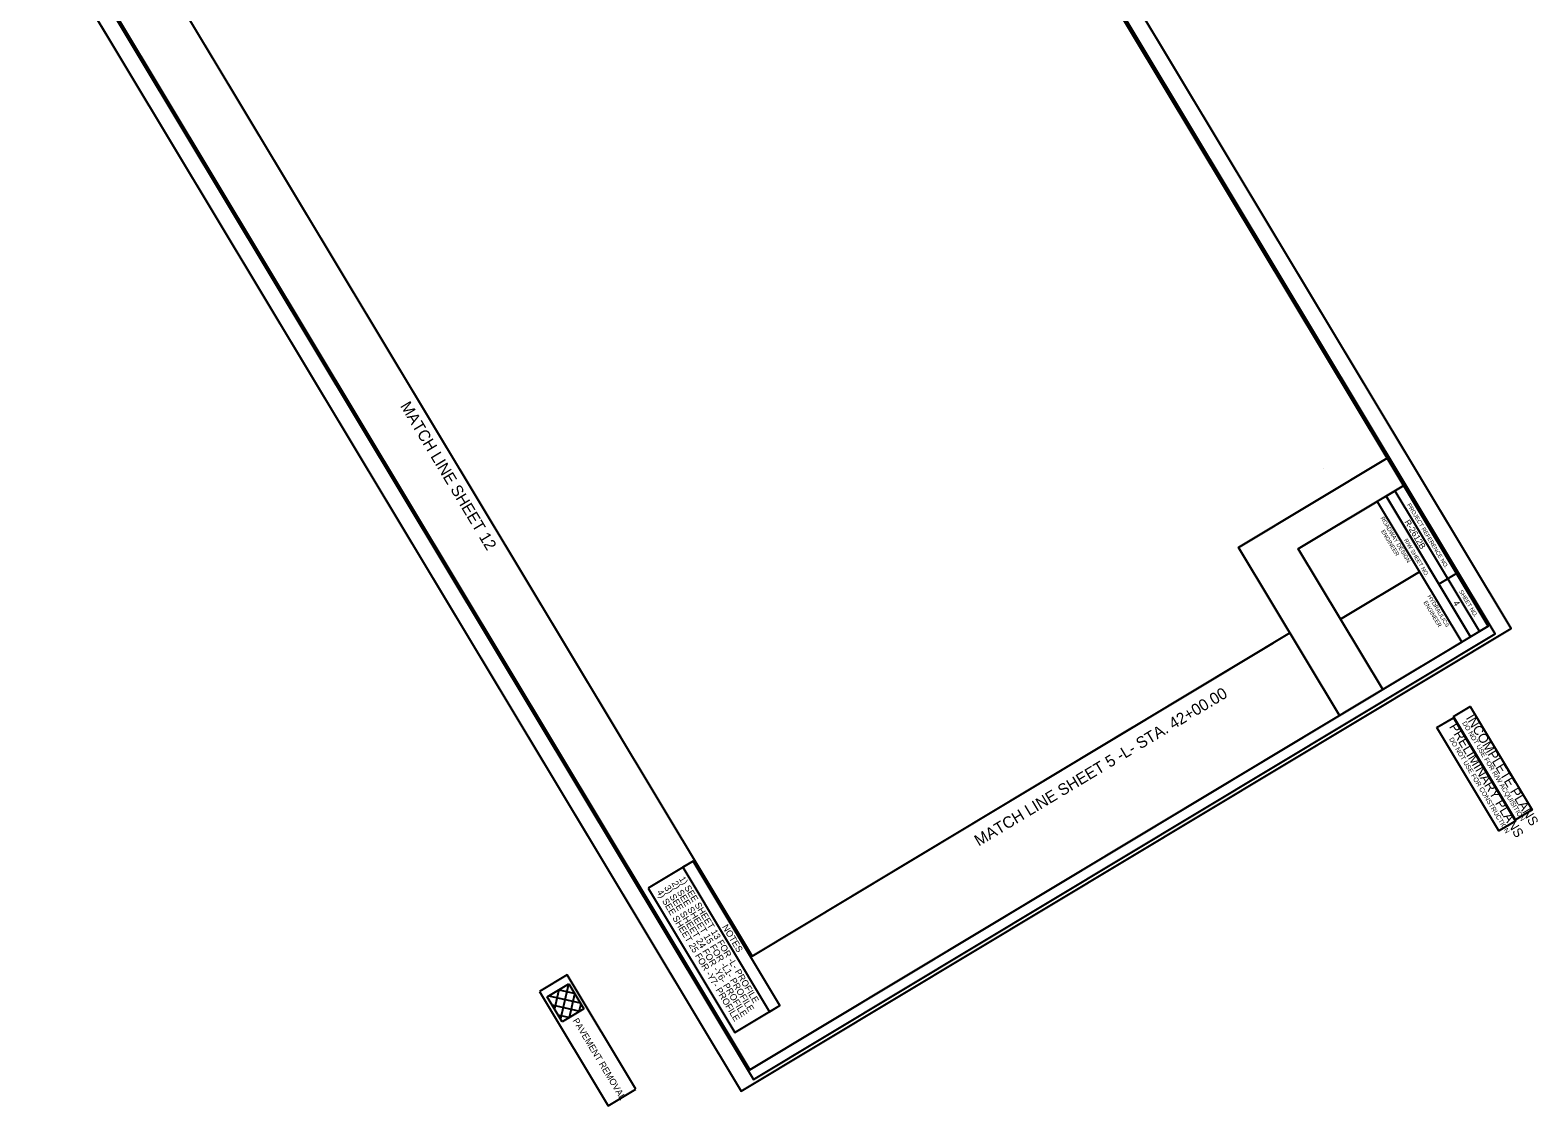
# Model space of a CAD drawing. Extents: x 1779635 to 1781473, y 814562 to 816692.
# Drawn here: x 1779635 to 1781473, y 814562 to 815873 of the extents above; entities that cross this region are included whole.
import ezdxf

# ---------------------------------------------------------------- set-up
doc = ezdxf.new("R2010")
doc.units = 0
for name, color, linetype in [('Matchline', 7, 'Continuous'), ('Matchline Text', 7, 'Continuous'), ('Prop DSN Text', 7, 'Continuous'), ('Prop Grid Mask', 7, 'Continuous'), ('Prop Rem of Exist Asph Pvmt', 7, 'Continuous'), ('Sheet Clip Boundary CELL', 7, 'Continuous'), ('Sheet Cutting Line CELL', 7, 'Continuous'), ('Sheet Data Field CELL', 7, 'Continuous'), ('Sheet North Arrow Point CELL', 7, 'Continuous'), ('Sheet Plan CELL', 7, 'Continuous'), ('Sheet Plan Layout CELL', 7, 'Continuous'), ('Sheet Plot Border Inside CELL', 7, 'Continuous'), ('Sheet Plot Border Outside CELL', 7, 'Continuous'), ('Sheet Sticker Incomplete CELL', 7, 'Continuous'), ('Sheet Sticker Preliminary CELL', 7, 'Continuous')]:
    doc.layers.add(name, color=color, linetype=linetype)

msp = doc.modelspace()

# ---------------------------------------------------------------- linework, layer by layer
at = {"layer": 'Matchline'}
for p, q in [((1779847.9, 815854.8), (1780355.1, 815010.8)), ((1780636.5, 814817.2), (1781150.8, 815126.2)), ((1780722.2, 814868.7), (1780979.3, 815023.2))]:
    msp.add_line(p, q, dxfattribs=at)
at = {"layer": 'Prop Grid Mask'}
for p, q in [((1780289.5, 814721.3), (1780255.9, 814701.1)), ((1780373.3, 814581.9), (1780289.5, 814721.3)), ((1780255.9, 814701.1), (1780339.7, 814561.7)), ((1780339.7, 814561.7), (1780373.3, 814581.9))]:
    msp.add_line(p, q, dxfattribs=at)
for points in [[(1780388.4, 814827.2), (1780494.2, 814651.1), (1780549, 814684), (1780443.1, 814860.1)], [(1780430.6, 814852.6), (1780536.5, 814676.5), (1780549, 814684), (1780443.1, 814860.1)]]:
    msp.add_lwpolyline(points, close=True, dxfattribs=at)
at = {"layer": 'Prop Rem of Exist Asph Pvmt'}
for p, q in [((1780265.3, 814694.6), (1780291.6, 814710.4)), ((1780291.1, 814709.9), (1780281.5, 814667.6)), ((1780291.6, 814710.4), (1780309.9, 814679.8)), ((1780283.6, 814664), (1780265.3, 814694.6)), ((1780267.4, 814695.8), (1780305.3, 814687.2)), ((1780279.3, 814703), (1780274, 814680)), ((1780279.8, 814703.3), (1780297.8, 814699.2)), ((1780298.6, 814697.9), (1780292.1, 814669.1)), ((1780271.2, 814684.7), (1780305.2, 814677)), ((1780278.3, 814672.8), (1780292.8, 814669.6)), ((1780309.9, 814679.8), (1780283.6, 814664)), ((1780306.2, 814686.1), (1780304, 814676.2))]:
    msp.add_line(p, q, dxfattribs=at)
at = {"layer": 'Sheet Clip Boundary CELL'}
msp.add_lwpolyline([(1779828.9, 815886.5), (1780515.2, 814744.3), (1781170.7, 815138.2), (1781108, 815242.6), (1781289.3, 815351.5), (1780665.7, 816389.4)], close=True, dxfattribs=at)
at = {"layer": 'Sheet Cutting Line CELL'}
for p, q in [((1781440.5, 815143.5), (1780573.5, 816586.5)), ((1779634.9, 816022.5), (1780501.9, 814579.5))]:
    msp.add_line(p, q, dxfattribs=at)
at = {"layer": 'Sheet North Arrow Point CELL'}
msp.add_line((1781211.9, 815338.7), (1781211.9, 815338.7), dxfattribs=at)
at = {"layer": 'Sheet Plan CELL'}
for p, q in [((1781288, 815305), (1781277.3, 815298.6)), ((1781288, 815305), (1781391, 815133.6)), ((1781288, 815305), (1781391, 815133.6)), ((1781298.7, 815311.5), (1781401.8, 815140)), ((1781328.8, 815212.8), (1781232.4, 815154.9)), ((1781373.8, 815210.7), (1781352.4, 815197.8))]:
    msp.add_line(p, q, dxfattribs=at)
for points in [[(1781412.5, 815146.4), (1780640, 816432.2), (1779739.9, 815891.4), (1780512.5, 814605.7)], [(1779739.9, 815891.4), (1780639.9, 816432.2), (1781309.5, 815317.9), (1781180.9, 815240.6), (1781283.9, 815069.2), (1780512.5, 814605.7)], [(1781309.5, 815317.9), (1781412.5, 815146.4), (1781391, 815133.6), (1781288, 815305)], [(1781277.3, 815298.6), (1781328.8, 815212.8), (1781232.4, 815154.9), (1781180.9, 815240.6)], [(1781328.8, 815212.8), (1781380.3, 815127.1), (1781283.9, 815069.2), (1781232.4, 815154.9)]]:
    msp.add_lwpolyline(points, close=True, dxfattribs=at)
at = {"layer": 'Sheet Plan Layout CELL'}
for points in [[(1780639.9, 816432.2), (1779739.9, 815891.4), (1780512.5, 814605.7), (1781231.2, 815037.5), (1781108, 815242.6), (1781289.3, 815351.5)], [(1781108, 815242.6), (1781231.2, 815037.5), (1781412.5, 815146.4), (1781289.3, 815351.5)]]:
    msp.add_lwpolyline(points, close=True, dxfattribs=at)
at = {"layer": 'Sheet Plot Border Inside CELL'}
msp.add_lwpolyline([(1779658.7, 816021.7), (1780516.8, 814593.7), (1781421.1, 815137), (1780563, 816565.1)], close=True, dxfattribs=at)
at = {"layer": 'Sheet Plot Border Outside CELL'}
msp.add_lwpolyline([(1779634.9, 816022.5), (1780501.9, 814579.5), (1781440.5, 815143.5), (1780573.5, 816586.5)], close=True, dxfattribs=at)
at = {"layer": 'Sheet Sticker Incomplete CELL'}
msp.add_lwpolyline([(1781370.3, 815036.4), (1781390.4, 815048.5), (1781466.1, 814922.5), (1781446, 814910.4)], close=True, dxfattribs=at)
at = {"layer": 'Sheet Sticker Preliminary CELL'}
msp.add_lwpolyline([(1781350, 815022.8), (1781370.1, 815034.9), (1781445.8, 814908.9), (1781425.7, 814896.8)], close=True, dxfattribs=at)

# ---------------------------------------------------------------- texts
at = {"layer": 'Matchline Text'}
for s, rotation, p in [('MATCH LINE SHEET 12', 301, (1780085.6, 815415.1)), ('MATCH LINE SHEET 5 -L- STA. 42+00.00', 31, (1780791.4, 814877.7)), ('MATCH LINE SHEET 5 -L- STA. 42+00.00', 31, (1780791.4, 814877.7))]:
    msp.add_text(s, height=14, rotation=rotation, dxfattribs=at).set_placement(p)
at = {"layer": 'Prop DSN Text'}
for s, height, p in [('2) SEE SHEET 15 FOR -L1- PROFILE ', 8, (1780416.6, 814833.1)), ('1) SEE SHEET 13 FOR -L- PROFILE', 8, (1780425.6, 814838.5)), ('4) SEE SHEET 25 FOR -Y7- PROFILE', 8, (1780398.6, 814822.3)), ('3) SEE SHEET 24 FOR -Y6- PROFILE', 8, (1780407.6, 814827.7)), ('NOTES', 8.1, (1780478.2, 814779.9)), ('PAVEMENT REMOVAL', 8, (1780296, 814665.7))]:
    msp.add_text(s, height=height, rotation=301, dxfattribs=at).set_placement(p)
at = {"layer": 'Sheet Data Field CELL'}
for s, p in [('R-2612B  ', (1781310.1, 815273.5)), ('4  ', (1781369.4, 815174.9))]:
    msp.add_text(s, height=7.5, rotation=301, dxfattribs=at).set_placement(p)
at = {"layer": 'Sheet Plan CELL'}
for s, p in [('PROJECT REFERENCE NO.', (1781313.4, 815294.4)), ('ROADWAY DESIGN', (1781281, 815278.2)), ('ENGINEER', (1781281.7, 815262.3)), ('R/W SHEET NO.', (1781309.5, 815251.4)), ('HYDRAULICS', (1781338.3, 815183)), ('SHEET NO.', (1781376.8, 815188.8)), ('ENGINEER', (1781333.4, 815175.6))]:
    msp.add_text(s, height=5, rotation=301, dxfattribs=at).set_placement(p)
at = {"layer": 'Sheet Sticker Incomplete CELL'}
for s, height, p in [('INCOMPLETE PLANS', 11.52, (1781384.9, 815034.7)), ('DO NOT USE FOR R/W ACQUISITION', 5.76, (1781380.6, 815028.4))]:
    msp.add_text(s, height=height, rotation=301, dxfattribs=at).set_placement(p)
at = {"layer": 'Sheet Sticker Preliminary CELL'}
for s, height, p in [('PRELIMINARY PLANS', 11.52, (1781364.6, 815024)), ('DO NOT USE FOR CONSTRUCTION', 5.76, (1781364.7, 815008.8))]:
    msp.add_text(s, height=height, rotation=301, dxfattribs=at).set_placement(p)

doc.saveas('drawing.dxf')
